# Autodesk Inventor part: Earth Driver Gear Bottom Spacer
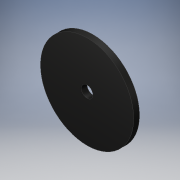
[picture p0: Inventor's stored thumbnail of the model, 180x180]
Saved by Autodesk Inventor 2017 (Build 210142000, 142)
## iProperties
Created: 2016-07
Part Number: Earth Driver Gear Bottom Spacer
Material: Generic
Document SubType Name: Modeling
Designer: Stan
Density: 1 g/cm^3
Appearance: Glossy - Black
Author: Stan
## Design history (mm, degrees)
sketch "Sketch1"
  geometry: C1 r 25.4 at (0, 0); C2 r 3.175 at (0, 0); 1 further point
  constraints: 2 centre point, 2 coincident
  dimensions: "d0" = 50.8 diameter of C1; "d1" = 6.35 diameter of C2
extrude "Extrusion1" new body sketch "Sketch1" distance "d2" = 3.175; taper "d3" = 0 deg
body "Solid1"
